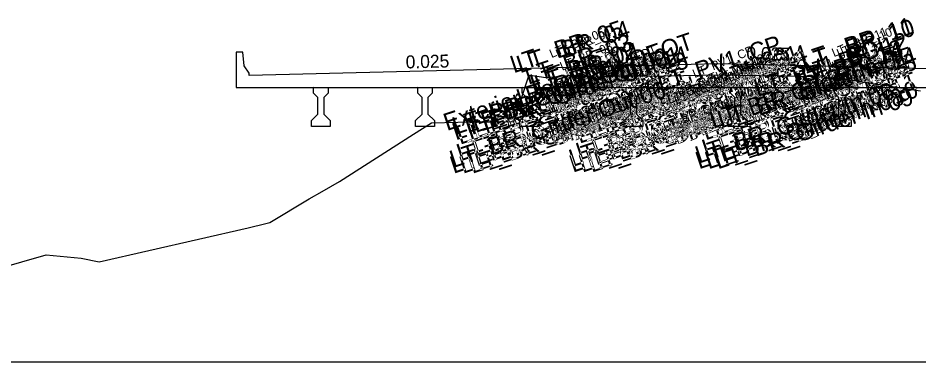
# Model space of a CAD drawing. Extents: x -26 to 2603, y -10 to 9566.
# Drawn here: x 1192.4 to 1296.1, y 6000 to 6039.6 of the extents above; entities that cross this region are included whole.
import ezdxf

# ---------------------------------------------------------------- set-up
doc = ezdxf.new("R2010")
doc.units = 0
for name, color, linetype in [('Exist Cross Section Cell', 7, 'Continuous'), ('Exist XS Ground Line', 7, 'Continuous'), ('Prop CMT Concrete Structures', 7, 'Continuous'), ('Prop XS SE Text', 7, 'Continuous'), ('Scratch_Level_9', 7, 'Continuous')]:
    doc.layers.add(name, color=color, linetype=linetype)

msp = doc.modelspace()

# ---------------------------------------------------------------- linework, layer by layer
at = {"layer": 'Exist Cross Section Cell'}
msp.add_line((1000, 6000), (1300, 6000), dxfattribs=at)
at = {"layer": 'Exist XS Ground Line'}
for p, q in [((1251.14, 6032.85), (1251.34, 6033.06)), ((1251.34, 6033.06), (1253.14, 6032.79)), ((1253.14, 6032.79), (1256.02, 6033.05)), ((1256.02, 6033.05), (1258.21, 6032.87)), ((1266.88, 6033), (1273.26, 6033.08)), ((1273.26, 6033.08), (1280.09, 6032.98)), ((1249.48, 6027.73), (1251.14, 6032.85)), ((1258.21, 6032.87), (1258.74, 6032.88)), ((1258.74, 6032.88), (1260.67, 6032.93)), ((1260.67, 6032.93), (1266.88, 6033)), ((1280.09, 6032.98), (1283.97, 6032.92)), ((1283.97, 6032.92), (1285.22, 6032.88)), ((1285.22, 6032.88), (1286.29, 6032.61)), ((1286.29, 6032.61), (1287.31, 6032.59)), ((1287.31, 6032.59), (1288.76, 6032.44)), ((1288.76, 6032.44), (1290.32, 6032.19)), ((1290.32, 6032.19), (1295.07, 6031.43)), ((1295.07, 6031.43), (1295.75, 6031.35)), ((1295.75, 6031.35), (1296.3, 6031.26)), ((1237.92, 6026.27), (1240, 6027.56)), ((1240, 6027.56), (1243.03, 6027.64)), ((1243.03, 6027.64), (1244.59, 6027.68)), ((1244.59, 6027.68), (1245.25, 6027.69)), ((1245.25, 6027.69), (1246.74, 6027.67)), ((1246.74, 6027.67), (1249.48, 6027.73)), ((1229.38, 6020.8), (1237.92, 6026.27)), ((1227.41, 6019.67), (1229.38, 6020.8)), ((1225.89, 6018.8), (1227.41, 6019.67)), ((1221.38, 6016.09), (1225.89, 6018.8)), ((1201.69, 6011.56), (1218.88, 6015.48)), ((1218.88, 6015.48), (1220.9, 6015.95)), ((1220.9, 6015.95), (1221.38, 6016.09)), ((1189.11, 6010.48), (1195.62, 6012.36)), ((1195.62, 6012.36), (1199.62, 6011.97)), ((1199.62, 6011.97), (1201.69, 6011.56))]:
    msp.add_line(p, q, dxfattribs=at)
at = {"layer": 'Prop CMT Concrete Structures'}
for points in [[(1272.98, 6034.38), (1219, 6033.04), (1218.99, 6033.29), (1218.41, 6034.12), (1218.24, 6035.7), (1217.5, 6035.7), (1217.5, 6031.65)], [(1299.98, 6033.71), (1284.98, 6034.08), (1272.98, 6034.38)], [(1299.98, 6033.71), (1284.98, 6034.08), (1272.98, 6034.38)], [(1299.98, 6033.71), (1284.98, 6034.08), (1272.98, 6034.38)], [(1217.5, 6031.65), (1261, 6031.65), (1285, 6031.65), (1289.5, 6031.65)], [(1219, 6031.65), (1261, 6031.65), (1285, 6031.65), (1289.5, 6031.65)], [(1219, 6031.65), (1261, 6031.65), (1285, 6031.65), (1289.5, 6031.65)], [(1226.41, 6030.99), (1226.41, 6031.66)], [(1226.41, 6031.66), (1227.24, 6031.65), (1228.08, 6031.65)], [(1226.41, 6030.99), (1226.41, 6031.66)], [(1226.41, 6031.66), (1227.24, 6031.65), (1228.08, 6031.65)], [(1226.41, 6030.99), (1226.41, 6031.66)], [(1226.41, 6031.66), (1227.24, 6031.65), (1228.08, 6031.65)], [(1226.91, 6030.49), (1226.41, 6030.99)], [(1226.91, 6030.49), (1226.41, 6030.99)], [(1226.91, 6030.49), (1226.41, 6030.99)], [(1228.08, 6030.99), (1227.58, 6030.49)], [(1228.08, 6030.99), (1227.58, 6030.49)], [(1228.08, 6030.99), (1227.58, 6030.49)], [(1228.08, 6031.65), (1228.08, 6030.99)], [(1228.08, 6031.65), (1228.08, 6030.99)], [(1228.08, 6031.65), (1228.08, 6030.99)], [(1238.41, 6030.99), (1238.41, 6031.66)], [(1238.41, 6031.66), (1239.24, 6031.65), (1240.08, 6031.65)], [(1238.41, 6030.99), (1238.41, 6031.66)], [(1238.41, 6031.66), (1239.24, 6031.65), (1240.08, 6031.65)], [(1238.41, 6030.99), (1238.41, 6031.66)], [(1238.41, 6031.66), (1239.24, 6031.65), (1240.08, 6031.65)], [(1238.91, 6030.49), (1238.41, 6030.99)], [(1238.91, 6030.49), (1238.41, 6030.99)], [(1238.91, 6030.49), (1238.41, 6030.99)], [(1240.08, 6030.99), (1239.58, 6030.49)], [(1240.08, 6030.99), (1239.58, 6030.49)], [(1240.08, 6030.99), (1239.58, 6030.49)], [(1240.08, 6031.65), (1240.08, 6030.99)], [(1240.08, 6031.65), (1240.08, 6030.99)], [(1240.08, 6031.65), (1240.08, 6030.99)], [(1250.41, 6030.99), (1250.41, 6031.66)], [(1250.41, 6031.66), (1251.24, 6031.65), (1252.08, 6031.65)], [(1250.41, 6030.99), (1250.41, 6031.66)], [(1250.41, 6031.66), (1251.24, 6031.65), (1252.08, 6031.65)], [(1250.41, 6030.99), (1250.41, 6031.66)], [(1250.41, 6031.66), (1251.24, 6031.65), (1252.08, 6031.65)], [(1250.91, 6030.49), (1250.41, 6030.99)], [(1250.91, 6030.49), (1250.41, 6030.99)], [(1250.91, 6030.49), (1250.41, 6030.99)], [(1252.08, 6030.99), (1251.58, 6030.49)], [(1252.08, 6030.99), (1251.58, 6030.49)], [(1252.08, 6030.99), (1251.58, 6030.49)], [(1252.08, 6031.65), (1252.08, 6030.99)], [(1252.08, 6031.65), (1252.08, 6030.99)], [(1252.08, 6031.65), (1252.08, 6030.99)], [(1256.5, 6031.65), (1261, 6031.65), (1285, 6031.65), (1315, 6031.65)], [(1256.5, 6031.65), (1261, 6031.65), (1285, 6031.65), (1315, 6031.65)], [(1256.5, 6031.65), (1261, 6031.65), (1285, 6031.65), (1315, 6031.65)], [(1260.46, 6031.65), (1259.62, 6031.65), (1258.79, 6031.65)], [(1260.46, 6031.65), (1259.62, 6031.65), (1258.79, 6031.65)], [(1260.46, 6031.65), (1259.62, 6031.65), (1258.79, 6031.65)], [(1262.41, 6030.99), (1262.41, 6031.66)], [(1262.41, 6031.66), (1263.24, 6031.65), (1264.08, 6031.65)], [(1262.41, 6030.99), (1262.41, 6031.66)], [(1262.41, 6031.66), (1263.24, 6031.65), (1264.08, 6031.65)], [(1262.41, 6030.99), (1262.41, 6031.66)], [(1262.41, 6031.66), (1263.24, 6031.65), (1264.08, 6031.65)], [(1262.91, 6030.49), (1262.41, 6030.99)], [(1262.91, 6030.49), (1262.41, 6030.99)], [(1262.91, 6030.49), (1262.41, 6030.99)], [(1264.08, 6030.99), (1263.58, 6030.49)], [(1264.08, 6030.99), (1263.58, 6030.49)], [(1264.08, 6030.99), (1263.58, 6030.49)], [(1264.08, 6031.65), (1264.08, 6030.99)], [(1264.08, 6031.65), (1264.08, 6030.99)], [(1264.08, 6031.65), (1264.08, 6030.99)], [(1273.83, 6031.65), (1273, 6031.65), (1272.17, 6031.65)], [(1273.83, 6031.65), (1273, 6031.65), (1272.17, 6031.65)], [(1273.83, 6031.65), (1273, 6031.65), (1272.17, 6031.65)], [(1274.41, 6030.99), (1274.41, 6031.66)], [(1274.41, 6031.66), (1275.24, 6031.65), (1276.08, 6031.65)], [(1274.41, 6030.99), (1274.41, 6031.66)], [(1274.41, 6031.66), (1275.24, 6031.65), (1276.08, 6031.65)], [(1274.41, 6030.99), (1274.41, 6031.66)], [(1274.41, 6031.66), (1275.24, 6031.65), (1276.08, 6031.65)], [(1274.91, 6030.49), (1274.41, 6030.99)], [(1274.91, 6030.49), (1274.41, 6030.99)], [(1274.91, 6030.49), (1274.41, 6030.99)], [(1276.08, 6030.99), (1275.58, 6030.49)], [(1276.08, 6030.99), (1275.58, 6030.49)], [(1276.08, 6030.99), (1275.58, 6030.49)], [(1276.08, 6031.65), (1276.08, 6030.99)], [(1276.08, 6031.65), (1276.08, 6030.99)], [(1276.08, 6031.65), (1276.08, 6030.99)], [(1287.21, 6031.65), (1286.38, 6031.65), (1285.54, 6031.65)], [(1287.21, 6031.65), (1286.38, 6031.65), (1285.54, 6031.65)], [(1287.21, 6031.65), (1286.38, 6031.65), (1285.54, 6031.65)], [(1286.41, 6030.99), (1286.41, 6031.66)], [(1286.41, 6031.66), (1287.24, 6031.65), (1288.08, 6031.65)], [(1286.41, 6030.99), (1286.41, 6031.66)], [(1286.41, 6031.66), (1287.24, 6031.65), (1288.08, 6031.65)], [(1286.41, 6030.99), (1286.41, 6031.66)], [(1286.41, 6031.66), (1287.24, 6031.65), (1288.08, 6031.65)], [(1286.91, 6030.49), (1286.41, 6030.99)], [(1286.91, 6030.49), (1286.41, 6030.99)], [(1286.91, 6030.49), (1286.41, 6030.99)], [(1288.08, 6030.99), (1287.58, 6030.49)], [(1288.08, 6030.99), (1287.58, 6030.49)], [(1288.08, 6030.99), (1287.58, 6030.49)], [(1288.08, 6031.65), (1288.08, 6030.99)], [(1288.08, 6031.65), (1288.08, 6030.99)], [(1288.08, 6031.65), (1288.08, 6030.99)], [(1226.91, 6028.57), (1226.91, 6030.49)], [(1226.91, 6028.57), (1226.91, 6030.49)], [(1226.91, 6028.57), (1226.91, 6030.49)], [(1227.58, 6030.49), (1227.58, 6028.57)], [(1227.58, 6030.49), (1227.58, 6028.57)], [(1227.58, 6030.49), (1227.58, 6028.57)], [(1238.91, 6028.57), (1238.91, 6030.49)], [(1238.91, 6028.57), (1238.91, 6030.49)], [(1238.91, 6028.57), (1238.91, 6030.49)], [(1239.58, 6030.49), (1239.58, 6028.57)], [(1239.58, 6030.49), (1239.58, 6028.57)], [(1239.58, 6030.49), (1239.58, 6028.57)], [(1250.91, 6028.57), (1250.91, 6030.49)], [(1250.91, 6028.57), (1250.91, 6030.49)], [(1250.91, 6028.57), (1250.91, 6030.49)], [(1251.58, 6030.49), (1251.58, 6028.57)], [(1251.58, 6030.49), (1251.58, 6028.57)], [(1251.58, 6030.49), (1251.58, 6028.57)], [(1262.91, 6028.57), (1262.91, 6030.49)], [(1262.91, 6028.57), (1262.91, 6030.49)], [(1262.91, 6028.57), (1262.91, 6030.49)], [(1263.58, 6030.49), (1263.58, 6028.57)], [(1263.58, 6030.49), (1263.58, 6028.57)], [(1263.58, 6030.49), (1263.58, 6028.57)], [(1274.91, 6028.57), (1274.91, 6030.49)], [(1274.91, 6028.57), (1274.91, 6030.49)], [(1274.91, 6028.57), (1274.91, 6030.49)], [(1275.58, 6030.49), (1275.58, 6028.57)], [(1275.58, 6030.49), (1275.58, 6028.57)], [(1275.58, 6030.49), (1275.58, 6028.57)], [(1286.91, 6028.57), (1286.91, 6030.49)], [(1286.91, 6028.57), (1286.91, 6030.49)], [(1286.91, 6028.57), (1286.91, 6030.49)], [(1287.58, 6030.49), (1287.58, 6028.57)], [(1287.58, 6030.49), (1287.58, 6028.57)], [(1287.58, 6030.49), (1287.58, 6028.57)], [(1226.16, 6027.82), (1226.91, 6028.57)], [(1226.16, 6027.82), (1226.91, 6028.57)], [(1226.16, 6027.82), (1226.91, 6028.57)], [(1227.58, 6028.57), (1228.33, 6027.82)], [(1227.58, 6028.57), (1228.33, 6027.82)], [(1227.58, 6028.57), (1228.33, 6027.82)], [(1238.16, 6027.82), (1238.91, 6028.57)], [(1238.16, 6027.82), (1238.91, 6028.57)], [(1238.16, 6027.82), (1238.91, 6028.57)], [(1239.58, 6028.57), (1240.33, 6027.82)], [(1239.58, 6028.57), (1240.33, 6027.82)], [(1239.58, 6028.57), (1240.33, 6027.82)], [(1250.16, 6027.82), (1250.91, 6028.57)], [(1250.16, 6027.82), (1250.91, 6028.57)], [(1250.16, 6027.82), (1250.91, 6028.57)], [(1251.58, 6028.57), (1252.33, 6027.82)], [(1251.58, 6028.57), (1252.33, 6027.82)], [(1251.58, 6028.57), (1252.33, 6027.82)], [(1262.16, 6027.82), (1262.91, 6028.57)], [(1262.16, 6027.82), (1262.91, 6028.57)], [(1262.16, 6027.82), (1262.91, 6028.57)], [(1263.58, 6028.57), (1264.33, 6027.82)], [(1263.58, 6028.57), (1264.33, 6027.82)], [(1263.58, 6028.57), (1264.33, 6027.82)], [(1274.16, 6027.82), (1274.91, 6028.57)], [(1274.16, 6027.82), (1274.91, 6028.57)], [(1274.16, 6027.82), (1274.91, 6028.57)], [(1275.58, 6028.57), (1276.33, 6027.82)], [(1275.58, 6028.57), (1276.33, 6027.82)], [(1275.58, 6028.57), (1276.33, 6027.82)], [(1286.16, 6027.82), (1286.91, 6028.57)], [(1286.16, 6027.82), (1286.91, 6028.57)], [(1286.16, 6027.82), (1286.91, 6028.57)], [(1287.58, 6028.57), (1288.33, 6027.82)], [(1287.58, 6028.57), (1288.33, 6027.82)], [(1287.58, 6028.57), (1288.33, 6027.82)], [(1226.16, 6027.15), (1226.16, 6027.82)], [(1226.16, 6027.15), (1226.16, 6027.82)], [(1226.16, 6027.15), (1226.16, 6027.82)], [(1228.33, 6027.15), (1227.24, 6027.15), (1226.16, 6027.15)], [(1228.33, 6027.15), (1227.24, 6027.15), (1226.16, 6027.15)], [(1228.33, 6027.15), (1227.24, 6027.15), (1226.16, 6027.15)], [(1228.33, 6027.82), (1228.33, 6027.15)], [(1228.33, 6027.82), (1228.33, 6027.15)], [(1228.33, 6027.82), (1228.33, 6027.15)], [(1238.16, 6027.15), (1238.16, 6027.82)], [(1238.16, 6027.15), (1238.16, 6027.82)], [(1238.16, 6027.15), (1238.16, 6027.82)], [(1240.33, 6027.15), (1239.24, 6027.15), (1238.16, 6027.15)], [(1240.33, 6027.15), (1239.24, 6027.15), (1238.16, 6027.15)], [(1240.33, 6027.15), (1239.24, 6027.15), (1238.16, 6027.15)], [(1240.33, 6027.82), (1240.33, 6027.15)], [(1240.33, 6027.82), (1240.33, 6027.15)], [(1240.33, 6027.82), (1240.33, 6027.15)], [(1250.16, 6027.15), (1250.16, 6027.82)], [(1250.16, 6027.15), (1250.16, 6027.82)], [(1250.16, 6027.15), (1250.16, 6027.82)], [(1252.33, 6027.15), (1251.24, 6027.15), (1250.16, 6027.15)], [(1252.33, 6027.15), (1251.24, 6027.15), (1250.16, 6027.15)], [(1252.33, 6027.15), (1251.24, 6027.15), (1250.16, 6027.15)], [(1252.33, 6027.82), (1252.33, 6027.15)], [(1252.33, 6027.82), (1252.33, 6027.15)], [(1252.33, 6027.82), (1252.33, 6027.15)], [(1262.16, 6027.15), (1262.16, 6027.82)], [(1262.16, 6027.15), (1262.16, 6027.82)], [(1262.16, 6027.15), (1262.16, 6027.82)], [(1264.33, 6027.15), (1263.24, 6027.15), (1262.16, 6027.15)], [(1264.33, 6027.15), (1263.24, 6027.15), (1262.16, 6027.15)], [(1264.33, 6027.15), (1263.24, 6027.15), (1262.16, 6027.15)], [(1264.33, 6027.82), (1264.33, 6027.15)], [(1264.33, 6027.82), (1264.33, 6027.15)], [(1264.33, 6027.82), (1264.33, 6027.15)], [(1274.16, 6027.15), (1274.16, 6027.82)], [(1274.16, 6027.15), (1274.16, 6027.82)], [(1274.16, 6027.15), (1274.16, 6027.82)], [(1276.33, 6027.15), (1275.24, 6027.15), (1274.16, 6027.15)], [(1276.33, 6027.15), (1275.24, 6027.15), (1274.16, 6027.15)], [(1276.33, 6027.15), (1275.24, 6027.15), (1274.16, 6027.15)], [(1276.33, 6027.82), (1276.33, 6027.15)], [(1276.33, 6027.82), (1276.33, 6027.15)], [(1276.33, 6027.82), (1276.33, 6027.15)], [(1286.16, 6027.15), (1286.16, 6027.82)], [(1286.16, 6027.15), (1286.16, 6027.82)], [(1286.16, 6027.15), (1286.16, 6027.82)], [(1288.33, 6027.15), (1287.24, 6027.15), (1286.16, 6027.15)], [(1288.33, 6027.15), (1287.24, 6027.15), (1286.16, 6027.15)], [(1288.33, 6027.15), (1287.24, 6027.15), (1286.16, 6027.15)], [(1288.33, 6027.82), (1288.33, 6027.15)], [(1288.33, 6027.82), (1288.33, 6027.15)], [(1288.33, 6027.82), (1288.33, 6027.15)]]:
    msp.add_lwpolyline(points, dxfattribs=at)

# ---------------------------------------------------------------- texts
at = {"layer": 'Prop XS SE Text'}
for rotation, p in [(358.5679, (1276.23, 6034.85)), (1.4321, (1237.03, 6033.83))]:
    msp.add_text('0.025', height=1.5, rotation=rotation, dxfattribs=at).set_placement(p)
at = {"layer": 'Scratch_Level_9'}
for s, height, rotation, p in [('LT_ BR_05', 2, 18.4332, (1249.45, 6033.27)), ('LT_ BR_04', 2, 18.4332, (1250.19, 6033.27)), ('LT_ BR_11', 2, 18.4332, (1282.86, 6033.66)), ('LT_ BR_10', 2, 18.4332, (1282.99, 6033.45)), ('LT_ BR_05', 1, 22.5575, (1253.82, 6035.02)), ('LT_ BR_04', 1, 22.5575, (1254.55, 6035.02)), ('LT_ BR_11', 1, 22.5575, (1286.34, 6035.13)), ('LT_ BR_10', 1, 22.5575, (1286.91, 6035.06)), ('LT_BR_03', 2, 18.4332, (1251.13, 6031.95)), ('LT_PV1_OEOT', 2, 18.4332, (1252.53, 6030.21)), ('LT_PV1_CP', 2, 18.4332, (1266.37, 6031.12)), ('LT_PV1_PGL', 2, 18.4332, (1277.52, 6030.54)), ('LT_BR_12', 2, 18.4332, (1282.93, 6032.15)), ('LT_BR_Girder Out 02', 2, 18.4332, (1242.78, 6026.19)), ('LT_BR_Girder Out 01', 2, 18.4332, (1244.15, 6026.37)), ('LT_BR_Girder Out 14', 2, 18.4332, (1245.06, 6026.4)), ('LT_BR_02', 2, 18.4332, (1251.72, 6031.12)), ('LT_BR_01', 2, 18.4332, (1252.27, 6031.04)), ('LT_BR_03', 1, 22.5575, (1255.03, 6033.57)), ('LT_BR_Girder Mid 02', 2, 18.4332, (1256.53, 6026.32)), ('LT_PV1_OEOT', 1, 22.5575, (1257.37, 6032.04)), ('LT_BR_Girder Mid 01', 2, 18.4332, (1257.9, 6026.5)), ('LT_BR_Girder Mid 14', 2, 18.4332, (1258.81, 6026.52)), ('LT_PV1_CP', 1, 22.5575, (1270.3, 6032.72)), ('LT_BR_Girder In 01', 2, 18.4332, (1272.42, 6026.88)), ('LT_BR_Girder In 14', 2, 18.4332, (1273.33, 6026.91)), ('LT_PV1_PGL', 1, 22.5575, (1281.96, 6032.28)), ('LT_BR_14', 2, 18.4332, (1282.34, 6031.07)), ('LT_BR_13', 2, 18.4332, (1282.35, 6031.32)), ('LT_BR_12', 1, 22.5575, (1286.35, 6033.62)), ('LT_BR_Girder Out 03', 2, 18.4332, (1242.78, 6025.53)), ('LT_BR_Girder Out 12', 2, 18.4332, (1244.56, 6025.23)), ('LT_BR_Girder Out 13', 2, 18.4332, (1245.06, 6025.73)), ('LT_BR_06', 2, 18.4332, (1250.18, 6029.43)), ('LT_BR_Girder Out 02', 1, 22.5575, (1253.19, 6029.72)), ('LT_BR_Girder Out 01', 1, 22.5575, (1254.16, 6029.77)), ('LT_BR_07', 2, 18.4332, (1254.73, 6029.44)), ('LT_BR_Girder Out 14', 1, 22.5575, (1254.94, 6029.75)), ('LT_BR_02', 1, 22.5575, (1255.63, 6032.74)), ('LT_BR_01', 1, 22.5575, (1255.78, 6032.54)), ('LT_BR_Girder Mid 03', 2, 18.4332, (1256.53, 6025.65)), ('LT_BR_Girder Mid 04', 2, 18.4332, (1257.03, 6025.15)), ('LT_BR_Girder Mid 12', 2, 18.4332, (1258.31, 6025.36)), ('LT_BR_Girder Mid 13', 2, 18.4332, (1258.81, 6025.86)), ('LT_BR_Girder Mid 02', 1, 22.5575, (1266.43, 6029.66)), ('LT_BR_Girder Mid 01', 1, 22.5575, (1267.39, 6029.71)), ('LT_BR_Girder Mid 14', 1, 22.5575, (1268.17, 6029.69)), ('LT_BR_Girder In 02', 2, 18.4332, (1271.05, 6026.7)), ('LT_BR_Girder In 03', 2, 18.4332, (1271.05, 6026.04)), ('LT_BR_Girder In 13', 2, 18.4332, (1273.33, 6026.24)), ('LT_BR_08', 2, 18.4332, (1278.73, 6029.44)), ('LT_BR_Girder In 02', 1, 22.5575, (1280.3, 6029.87)), ('LT_BR_Girder In 01', 1, 22.5575, (1281.27, 6029.92)), ('LT_BR_Girder In 14', 1, 22.5575, (1282.05, 6029.9)), ('LT_BR_09', 2, 18.4332, (1283.23, 6029.44)), ('LT_BR_14', 1, 22.5575, (1285.72, 6032.52)), ('LT_BR_13', 1, 22.5575, (1285.75, 6032.78)), ('Exterior Boundary', 2, 18.4332, (1241.77, 6026.62)), ('LT_BR_Girder Out 04', 2, 18.4332, (1243.28, 6025.03)), ('Exterior Boundary', 1, 22.5575, (1251.76, 6030.08)), ('LT_BR_Girder Out 03', 1, 22.5575, (1253.17, 6029.04)), ('LT_BR_Girder Out 04', 1, 22.5575, (1253.66, 6028.54)), ('LT_BR_06', 1, 22.5575, (1254.11, 6031.05)), ('LT_BR_Girder Out 12', 1, 22.5575, (1254.46, 6028.6)), ('LT_BR_Girder Out 13', 1, 22.5575, (1254.95, 6029.09)), ('LT_BR_07', 1, 22.5575, (1258.6, 6031.05)), ('LT_BR_Girder Mid 03', 1, 22.5575, (1266.41, 6028.99)), ('LT_BR_Girder Mid 04', 1, 22.5575, (1266.9, 6028.48)), ('LT_BR_Girder Mid 12', 1, 22.5575, (1267.7, 6028.54)), ('LT_BR_Girder Mid 13', 1, 22.5575, (1268.19, 6029.03)), ('LT_BR_Girder In 04', 2, 18.4332, (1271.55, 6025.54)), ('LT_BR_Girder In 12', 2, 18.4332, (1272.83, 6025.74)), ('LT_BR_Girder In 03', 1, 22.5575, (1280.29, 6029.19)), ('LT_BR_Girder In 04', 1, 22.5575, (1280.77, 6028.69)), ('LT_BR_Girder In 12', 1, 22.5575, (1281.58, 6028.75)), ('LT_BR_Girder In 13', 1, 22.5575, (1282.06, 6029.24)), ('LT_BR_08', 1, 22.5575, (1282.61, 6031.05)), ('LT_BR_09', 1, 22.5575, (1287.12, 6031.05)), ('LT_BR_Girder Out 05', 2, 18.4332, (1243.28, 6023.11)), ('LT_BR_Girder Out 11', 2, 18.4332, (1245.09, 6023.49)), ('LT_BR_Girder Mid 05', 2, 18.4332, (1257.03, 6023.23)), ('LT_BR_Girder Mid 11', 2, 18.4332, (1258.84, 6023.62)), ('LT_BR_Girder In 11', 2, 18.4332, (1273.37, 6024)), ('LT_BR_Girder Out 06', 2, 18.4332, (1242.48, 6022.35)), ('LT_BR_Girder Out 10', 2, 18.4332, (1245.23, 6022.54)), ('LT_BR_Girder Out 05', 1, 22.5575, (1253.67, 6026.62)), ('LT_BR_Girder Out 11', 1, 22.5575, (1254.6, 6026.73)), ('LT_BR_Girder Mid 06', 2, 18.4332, (1256.23, 6022.47)), ('LT_BR_Girder Mid 10', 2, 18.4332, (1258.98, 6022.66)), ('LT_BR_Girder Mid 05', 1, 22.5575, (1266.9, 6026.57)), ('LT_BR_Girder Mid 11', 1, 22.5575, (1267.84, 6026.68)), ('LT_BR_Girder In 06', 2, 18.4332, (1270.76, 6022.85)), ('LT_BR_Girder In 05', 2, 18.4332, (1271.55, 6023.62)), ('LT_BR_Girder In 10', 2, 18.4332, (1273.51, 6023.05)), ('LT_BR_Girder In 05', 1, 22.5575, (1280.78, 6026.77)), ('LT_BR_Girder In 11', 1, 22.5575, (1281.71, 6026.89)), ('LT_BR_Girder Out 07', 2, 18.4332, (1242.53, 6021.69)), ('LT_BR_Girder Out 08', 2, 18.4332, (1243.61, 6021.69)), ('LT_BR_Girder Out 09', 2, 18.4332, (1244.69, 6021.69)), ('LT_BR_Girder Out 07', 1, 22.5575, (1252.9, 6025.2)), ('LT_BR_Girder Out 06', 1, 22.5575, (1252.91, 6025.87)), ('LT_BR_Girder Out 08', 1, 22.5575, (1253.99, 6025.2)), ('LT_BR_Girder Out 09', 1, 22.5575, (1255.08, 6025.21)), ('LT_BR_Girder Out 10', 1, 22.5575, (1255.18, 6025.91)), ('LT_BR_Girder Mid 07', 2, 18.4332, (1256.28, 6021.82)), ('LT_BR_Girder Mid 08', 2, 18.4332, (1257.36, 6021.82)), ('LT_BR_Girder Mid 09', 2, 18.4332, (1258.44, 6021.82)), ('LT_BR_Girder Mid 07', 1, 22.5575, (1266.14, 6025.14)), ('LT_BR_Girder Mid 06', 1, 22.5575, (1266.15, 6025.81)), ('LT_BR_Girder Mid 08', 1, 22.5575, (1267.23, 6025.15)), ('LT_BR_Girder Mid 09', 1, 22.5575, (1268.32, 6025.15)), ('LT_BR_Girder Mid 10', 1, 22.5575, (1268.42, 6025.86)), ('LT_BR_Girder In 07', 2, 18.4332, (1270.8, 6022.2)), ('LT_BR_Girder In 08', 2, 18.4332, (1271.89, 6022.2)), ('LT_BR_Girder In 09', 2, 18.4332, (1272.97, 6022.2)), ('LT_BR_Girder In 06', 1, 22.5575, (1280.03, 6026.02)), ('LT_BR_Girder In 10', 1, 22.5575, (1282.29, 6026.06)), ('LT_BR_Girder In 07', 1, 22.5575, (1280.01, 6025.35)), ('LT_BR_Girder In 08', 1, 22.5575, (1281.11, 6025.36)), ('LT_BR_Girder In 09', 1, 22.5575, (1282.19, 6025.36))]:
    msp.add_text(s, height=height, rotation=rotation, dxfattribs=at).set_placement(p)

doc.saveas('drawing.dxf')
